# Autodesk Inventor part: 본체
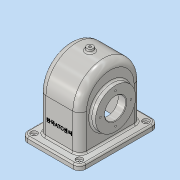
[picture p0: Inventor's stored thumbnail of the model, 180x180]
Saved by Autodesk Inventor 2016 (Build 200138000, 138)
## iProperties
Created: 2018-08
Part Number: 본체
Material: 알루미늄 6061
Document SubType Name: Modeling
Designer: Administrator
Density: 2.7 g/cm^3
Appearance: 알루미늄 - 평지
Mass: 1092.08 g
Surface Area: 1182.21 cm^2
Volume: 404.475 cm^3
Author: Administrator
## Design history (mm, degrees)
sketch "스케치1"
  geometry: L1 (43, -75)-(-43, -75); L2 (-55, -63)-(-55, 63); L3 (-43, 75)-(43, 75); L4 (55, 63)-(55, -63); L5 (55, -75)-(-55, 75); L6 (-55, -75)-(55, 75); A1 r 12 centre (-43, 63) between (-43, 75) and (-55, 63); A2 r 12 centre (-43, -63) between (-55, -63) and (-43, -75); A3 r 12 centre (43, -63) between (43, -75) and (55, -63); A4 r 12 centre (43, 63) between (55, 63) and (43, 75); 1 further point
  constraints: 12 end point, 8 point on circle, 8 point on line, 8 tangent, 4 centre point, 3 equal radius, 2 midpoint, 2 parallel, 1 horizontal, 1 perpendicular
  dimensions: "d0" = 110 distance of L5.end L6.end; "d1" = 150 distance of L6.start L5.end; "d2" = 12 radius of A1
extrude "돌출1" new body sketch "스케치1" distance "d3" = 10; taper "d4" = 0 deg
sketch "스케치2"
  geometry: L1 (0, 0)-(0, 78); L2 (62.428, 78)-(-77.21, 78); L3 (-52, 78)-(-52, 0); L4 (63, 0)-(-63, 0) reference; L5 (52, 78)-(52, 0); L6 (-58, 0)-(-58, 78); L7 (58, 78)-(58, 0); L8 (-58, 0)-(58, 0); A1 r 52 centre (0, 78) between (52, 78) and (-52, 78); A2 r 58 centre (0, 78) between (58, 78) and (-58, 78)
  constraints: 14 end point, 5 point on line, 4 point on circle, 2 centre point, 2 vertical, 1 coincident, 1 collinear, 1 horizontal, 1 symmetric about line, 2 other
  dimensions: "d8" = 52 radius of A1; "d9" = 78 distance of L3.start L3.end; "d10" = 6 radial gap between concentric circles of A1 A2
extrude "돌출2" join sketch "스케치2" stored distance "d11" = 77; taper "d12" = 0 deg
sketch "스케치3"
  geometry: L1 (0, 0)-(0, 65); L2 (0, 65)-(-48.5, 65); L3 (-48.5, 65)-(-48.5, 103); L4 (-48.5, 103)-(0, 103); L5 (0, 103)-(0, 65); L6 (-38.5, 136)-(-38.5, 78) reference
  constraints: 10 end point, 3 perpendicular, 1 horizontal, 1 vertical
  dimensions: "d13" = 65 distance of L1.start L1.end; "d14" = 76 diameter of L4 L2; "d15" = 10 distance between parallel lines of L3 L6
revolve "회전1" sketch "스케치3" stored, may be unused: angle "d16" = 90 deg
node "작업 평면1"
sketch "스케치4"
  geometry: C1 r 6 at (0, 0); 1 further point
  constraints: 1 centre point, 1 coincident
  dimensions: "d18" = 12 diameter of C1
extrude "돌출3" join sketch "스케치4" stored distance "d19" = 77; taper "d20" = 5 deg
sketch "스케치5"
  geometry: L1 (-58, 10)-(-58, 78) reference; L2 (58, 78)-(58, 10) reference; L3 (-52, 0)-(-52, 78); L4 (52, 78)-(52, 0); L5 (-52, 0)-(52, 0); L6 (63, 0)-(-63, 0) reference; L7 (-52, 78)-(52, 78); A1 r 58 centre (0, 78) between (58, 78) and (-58, 78) reference; A2 r 52 centre (0, 78) between (52, 78) and (-52, 78); 1 further point
  constraints: 8 end point, 2 point on circle, 2 point on line, 2 vertical, 1 centre point, 1 horizontal, 1 perpendicular
  dimensions: "d21" = 6 radial gap between concentric circles of A1 A2; "d22" = 78 distance of L3.start L3.end
extrude "돌출4" cut sketch "스케치5" stored distance "d23" = 67; taper "d24" = 0 deg
sketch "스케치6"
  geometry: L1 (0, 0)-(0, 65); L2 (19.5, 65)-(19.5, 93); L3 (19.5, 93)-(38.5, 108.943); L4 (38.5, 78)-(38.5, 136) reference; L5 (38.5, 108.943)-(38.5, 103); L6 (38.5, 103)-(43.5, 103); L7 (43.5, 103)-(43.5, 65); L8 (43.5, 65)-(19.5, 65); L9 (0, 65)-(58.179, 65)
  constraints: 16 end point, 2 horizontal, 2 perpendicular, 2 point on line, 2 vertical, 1 collinear
  dimensions: "d25" = 65 distance of L1.start L1.end; "d26" = 56 diameter of L2.end L8; "d27" = 50 deg angle of L3 L2; "d28" = 24 distance between parallel lines of L2 L7; "d29" = 76 diameter of L6 L8; "d30" = 5 distance of L5.end L6.end
revolve "회전2" sketch "스케치6" stored, may be unused: angle "d31" = 90 deg
sketch "스케치7"
  geometry: L1 (0, 0)-(0, 65); L2 (-48.5, 65)-(43.5, 65); L3 (43.5, 65)-(43.5, 85); L4 (43.5, 85)-(-48.5, 85); L5 (-48.5, 85)-(-48.5, 65); L6 (43.5, 27)-(43.5, 103) reference; L7 (-48.5, 27)-(-48.5, 103) reference
  constraints: 10 end point, 3 perpendicular, 2 midpoint, 1 horizontal, 1 point on line, 1 vertical
  dimensions: "d32" = 65 distance of L1.start L1.end; "d33" = 40 diameter of L4 L2
revolve "회전3" sketch "스케치7" stored, may be unused: angle "d34" = 90 deg
hole "구멍1" diameter "d37" = 5; stored, may be unused: countersink angle "d41" = 90 deg, drill point angle "d43" = 118 deg; dims "d35" = 10, "d36" = 10, "d38" = 6, "d39" = 12, "d40" = 4, "d42" = 8
hole "구멍2" diameter "d46" = 5; stored, may be unused: countersink angle "d50" = 90 deg, drill point angle "d52" = 118 deg; dims "d44" = 10, "d45" = 10, "d47" = 6, "d48" = 12, "d49" = 4, "d51" = 8
hole "구멍3" diameter "d55" = 5; stored, may be unused: countersink angle "d59" = 90 deg, drill point angle "d61" = 118 deg; dims "d53" = 10, "d54" = 10, "d56" = 6, "d57" = 12, "d58" = 4, "d60" = 8
hole "구멍4" diameter "d64" = 5; stored, may be unused: countersink angle "d68" = 90 deg, drill point angle "d70" = 118 deg; dims "d62" = 10, "d63" = 10, "d65" = 6, "d66" = 12, "d67" = 4, "d69" = 8
hole "구멍5" diameter "d73" = 4.459; stored, may be unused: countersink angle "d77" = 90 deg, drill point angle "d79" = 118 deg; dims "d71" = 10, "d72" = 10, "d74" = 10, "d75" = 12, "d76" = 4, "d78" = 12.8
sketch "스케치8" dims "d80" = 58
  geometry: L1 (0, 0)-(29, 0); C1 r 38 at (0, 0) reference; 5 further points
  constraints: 2 coincident, 2 end point, 1 horizontal, 1 horizontal alignment, 7 other
  dimensions: "d83" = 360 deg dimension on L1.start point (29, 0) (derived)
hole "구멍6" sketch "스케치8" at (29, 0), (0, 29), (-29, 0), (0, -29) diameter "d85" = 3.242; stored, may be unused: countersink angle "d89" = 90 deg, drill point angle "d91" = 118 deg; dims "d86" = 8, "d87" = 12, "d88" = 4, "d90" = 10
sketch "스케치9"
  geometry: L1 (0, 0)-(-29, 0); C1 r 38 at (0, 0) reference; C2 r 20 at (0, 0) reference; C3 r 29 at (0, 0); C4 r 1.621 at (-29, 0) reference; 5 further points
  constraints: 2 coincident, 2 end point, 1 centre point, 1 horizontal, 5 other
  dimensions: "d92" = 58 diameter of C3; "d95" = 360 deg dimension on C3.centre point (-29, 0) (derived)
hole "구멍7" sketch "스케치9" at (-29, 0), (0, -29), (29, 0), (0, 29) diameter "d97" = 3.242; stored, may be unused: countersink angle "d101" = 90 deg, drill point angle "d103" = 118 deg; dims "d98" = 8, "d99" = 12, "d100" = 4, "d102" = 10
sketch "스케치10"
  geometry: L1 (0, 68)-(0, 0) reference; L2 (5, -10)-(72, -10) reference; 2 further points
  constraints: 1 other
  dimensions: "d104" = 38.5 distance from line of L1 point (38.5, 30); "d105" = 40 distance from line of L2 point (38.5, 30)
feature "엠보싱1" sketch "스케치10" dims "d0" = 110, "d1" = 150, "d2" = 12, "d106" = 0.5, "d107" = 0
fillet "모깎기1" dims "d108" = 3
fillet "모깎기2" dims "d109" = 13
fillet "모깎기3" dims "d110" = 3
fillet "모깎기4" dims "d111" = 3
fillet "모깎기5" dims "d112" = 3
fillet "모깎기6" dims "d113" = 3
fillet "모깎기7" dims "d114" = 8
fillet "모깎기8" dims "d115" = 3
chamfer "모따기1" distance "d116" = 1; stored, may be unused: second distance "d117" = 2, angle "d118" = 45 deg
chamfer "모따기2" distance "d119" = 1; stored, may be unused: second distance "d120" = 2, angle "d121" = 45 deg
sketch "스케치11"
  geometry: L1 (98.23, 161.892)-(-86.936, 161.892); L2 (-86.936, 161.892)-(-86.936, -40.387); L3 (-86.936, -40.387)-(98.23, -40.387); L4 (98.23, -40.387)-(98.23, 161.892); 1 further point
  constraints: 8 end point, 2 parallel, 1 horizontal, 1 perpendicular
extrude "돌출5" cut sketch "스케치11" stored distance "d122" = 10; taper "d123" = 0 deg
node "솔리드1"
other parameters: "d17" = 142
